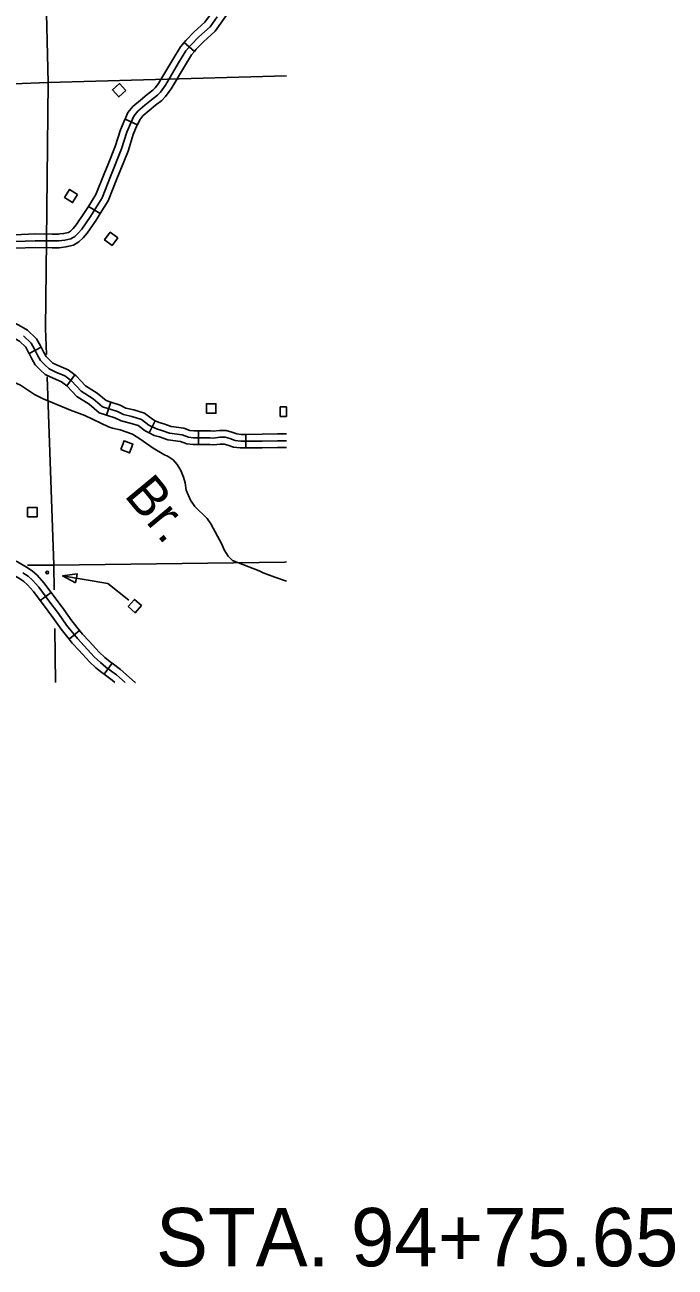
# Model space of a CAD drawing. Extents: x 1370130 to 1380143, y 377636 to 380256.
# Drawn here: x 1377687.4 to 1377888.1, y 378650.3 to 379033.5 of the extents above; entities that cross this region are included whole.
import ezdxf

# ---------------------------------------------------------------- set-up
doc = ezdxf.new("R2010")
doc.units = 0
for name, color, linetype in [('Level 31', 7, 'Continuous'), ('Level 32', 7, 'Continuous'), ('Level 35', 7, 'Continuous'), ('Level 5', 7, 'Continuous'), ('Level 56', 7, 'Continuous'), ('R_Draft', 7, 'Continuous')]:
    doc.layers.add(name, color=color, linetype=linetype)

msp = doc.modelspace()

# ---------------------------------------------------------------- linework, layer by layer
at = {"layer": 'Level 31'}
for p, q in [((1377736.53, 379028.04), (1377739.7, 379025.28)), ((1377722.12, 379002.71), (1377718.3, 379004.46)), ((1377707.05, 378977.5), (1377710.6, 378975.27)), ((1377698.71, 378964.83), (1377698.71, 378964.83))]:
    msp.add_line(p, q, dxfattribs=at)
for points in [[(1377736.53, 379028.04), (1377737.1, 379028.7), (1377739.64, 379031.32), (1377742.97, 379034.36), (1377744.96, 379037.13), (1377746.08, 379038.85)], [(1377684.37, 378966.69), (1377690.58, 378966.92), (1377695.79, 378966.84), (1377697.86, 378966.84), (1377699.7, 378967.07), (1377701.62, 378967.53), (1377702.77, 378968.22), (1377703.84, 378969.22), (1377704.92, 378970.52), (1377707.6, 378974.43), (1377711.2, 378980.19), (1377713.81, 378986.78), (1377717.26, 378995.29), (1377718.87, 379000.43), (1377720.17, 379003.5), (1377721.01, 379005.34), (1377722.24, 379006.88), (1377724.39, 379008.72), (1377726.46, 379010.4), (1377728.3, 379011.79), (1377729.22, 379012.78), (1377730.83, 379014.93), (1377734.81, 379021.76), (1377737.11, 379025.51), (1377738.65, 379027.28), (1377741.1, 379029.81), (1377744.55, 379032.95), (1377746.69, 379035.95)], [(1377739.7, 379025.28), (1377740.19, 379025.86), (1377742.56, 379028.3), (1377746.13, 379031.55), (1377748.43, 379034.76), (1377749.6, 379036.55)], [(1377728.58, 379015.43), (1377729.07, 379016.09), (1377733.01, 379022.83), (1377735.41, 379026.76), (1377736.53, 379028.04)], [(1377739.7, 379025.28), (1377738.81, 379024.27), (1377736.62, 379020.68), (1377732.58, 379013.77), (1377731.94, 379012.91)], [(1377718.3, 379004.46), (1377719.21, 379006.45), (1377720.72, 379008.34), (1377723.04, 379010.33), (1377725.16, 379012.06), (1377726.88, 379013.35), (1377727.6, 379014.13), (1377728.58, 379015.43)], [(1377731.94, 379012.91), (1377730.83, 379011.44), (1377729.71, 379010.22), (1377727.75, 379008.75), (1377725.74, 379007.11), (1377723.76, 379005.41), (1377722.82, 379004.23), (1377722.12, 379002.71)], [(1377713.07, 378990.55), (1377715.28, 378996), (1377716.9, 379001.16), (1377718.25, 379004.35), (1377718.3, 379004.46)], [(1377716.96, 378988.97), (1377719.24, 378994.59), (1377720.84, 378999.71), (1377722.09, 379002.65), (1377722.12, 379002.71)], [(1377707.05, 378977.5), (1377709.32, 378981.14), (1377711.86, 378987.56), (1377713.07, 378990.55)], [(1377710.6, 378975.27), (1377713.08, 378979.23), (1377715.76, 378986), (1377716.96, 378988.97)], [(1377698.19, 378969), (1377699.33, 378969.14), (1377700.82, 378969.5), (1377701.5, 378969.91), (1377702.31, 378970.66), (1377703.24, 378971.78), (1377705.84, 378975.58), (1377707.05, 378977.5)], [(1377710.6, 378975.27), (1377709.36, 378973.28), (1377706.6, 378969.26), (1377705.38, 378967.77), (1377704.04, 378966.53), (1377702.42, 378965.56), (1377700.08, 378965), (1377698.71, 378964.83)], [(1377683.52, 378968.73), (1377684.26, 378968.78), (1377690.56, 378969.02), (1377695.81, 378968.94), (1377697.73, 378968.94), (1377698.19, 378969)], [(1377698.71, 378964.83), (1377698, 378964.74), (1377695.78, 378964.74), (1377690.61, 378964.82), (1377684.49, 378964.59), (1377683.82, 378964.54)]]:
    msp.add_lwpolyline(points, dxfattribs=at)
at = {"layer": 'Level 32'}
for p, q in [((1377692.44, 378934.05), (1377688.73, 378932.09)), ((1377702.78, 378925.56), (1377700.32, 378922.16)), ((1377713.87, 378917.11), (1377712.58, 378913.12)), ((1377727.65, 378911.38), (1377725.79, 378907.62)), ((1377740.97, 378908.24), (1377740.97, 378904.04)), ((1377755.56, 378907.19), (1377755.58, 378902.99)), ((1377692.12, 378855.91), (1377695.48, 378858.44)), ((1377701.02, 378844.03), (1377704.29, 378846.66)), ((1377711.83, 378833.21), (1377714.31, 378836.6))]:
    msp.add_line(p, q, dxfattribs=at)
for points in [[(1377692.44, 378934.05), (1377692.22, 378934.47), (1377690.99, 378936.65), (1377688.22, 378939.29), (1377685.48, 378940.86), (1377684.09, 378941.56), (1377682.16, 378942.39), (1377679.17, 378942.97)], [(1377688.73, 378932.09), (1377688.53, 378932.46), (1377687.64, 378934.05), (1377685.69, 378935.9), (1377683.48, 378937.16), (1377682.31, 378937.76), (1377680.92, 378938.35), (1377678.36, 378938.85)], [(1377768.15, 378905.2), (1377765.38, 378905.2), (1377760.61, 378905.12), (1377754.02, 378905.08), (1377752.28, 378905.33), (1377750.66, 378905.87), (1377749.21, 378906.28), (1377747.55, 378906.28), (1377745.56, 378906.03), (1377744.57, 378906.14), (1377742.98, 378906.14), (1377739.44, 378906.14), (1377737.85, 378906.32), (1377735.9, 378907.03), (1377732.01, 378907.56), (1377729.62, 378908.39), (1377728.04, 378908.85), (1377725.64, 378910.04), (1377723.34, 378911.81), (1377720.44, 378912.68), (1377717.79, 378913.3), (1377715.99, 378914.22), (1377711.39, 378915.71), (1377708.48, 378918.18), (1377704.76, 378920.48), (1377701.82, 378923.67), (1377699.69, 378925.2), (1377696.98, 378926.38), (1377694.86, 378927.44), (1377693.56, 378928.62), (1377692.26, 378929.92), (1377691.44, 378931.46), (1377690.38, 378933.46), (1377689.31, 378935.35), (1377686.96, 378937.59)], [(1377700.32, 378922.16), (1377698.65, 378923.37), (1377696.09, 378924.48), (1377693.66, 378925.69), (1377692.11, 378927.1), (1377690.56, 378928.65), (1377689.58, 378930.47), (1377688.73, 378932.09)], [(1377702.78, 378925.56), (1377700.74, 378927.04), (1377697.87, 378928.28), (1377696.06, 378929.19), (1377695.01, 378930.14), (1377693.97, 378931.19), (1377693.29, 378932.44), (1377692.44, 378934.05)], [(1377713.87, 378917.11), (1377712.43, 378917.58), (1377709.72, 378919.88), (1377706.11, 378922.12), (1377703.22, 378925.25), (1377702.78, 378925.56)], [(1377712.58, 378913.12), (1377710.34, 378913.84), (1377707.24, 378916.48), (1377703.42, 378918.84), (1377700.42, 378922.09), (1377700.32, 378922.16)], [(1377727.65, 378911.38), (1377726.76, 378911.83), (1377724.32, 378913.71), (1377720.98, 378914.71), (1377718.51, 378915.29), (1377716.79, 378916.16), (1377713.87, 378917.11)], [(1377725.79, 378907.62), (1377724.52, 378908.25), (1377722.37, 378909.91), (1377719.9, 378910.65), (1377717.06, 378911.31), (1377715.18, 378912.27), (1377712.58, 378913.12)], [(1377740.97, 378908.24), (1377739.56, 378908.24), (1377738.33, 378908.38), (1377736.41, 378909.08), (1377732.5, 378909.61), (1377730.25, 378910.39), (1377728.8, 378910.81), (1377727.65, 378911.38)], [(1377740.97, 378904.04), (1377739.32, 378904.04), (1377737.37, 378904.26), (1377735.4, 378904.98), (1377731.52, 378905.51), (1377728.98, 378906.39), (1377727.28, 378906.88), (1377725.79, 378907.62)], [(1377755.56, 378907.19), (1377754.16, 378907.18), (1377752.76, 378907.38), (1377751.28, 378907.87), (1377749.5, 378908.38), (1377747.42, 378908.38), (1377745.55, 378908.15), (1377744.69, 378908.24), (1377742.98, 378908.24), (1377740.97, 378908.24)], [(1377755.58, 378902.99), (1377753.88, 378902.98), (1377751.79, 378903.27), (1377750.04, 378903.86), (1377748.92, 378904.18), (1377747.68, 378904.18), (1377745.57, 378903.92), (1377744.45, 378904.04), (1377742.98, 378904.04), (1377740.97, 378904.04)], [(1377768.15, 378907.3), (1377765.36, 378907.3), (1377760.59, 378907.22), (1377755.56, 378907.19)], [(1377768.15, 378903.1), (1377765.4, 378903.1), (1377760.64, 378903.02), (1377755.58, 378902.99)], [(1377683.12, 378868.6), (1377683.35, 378868.56), (1377685.15, 378867.9), (1377687.91, 378866.25), (1377689.64, 378865.1), (1377691.2, 378863.71), (1377693.28, 378861.36), (1377695.48, 378858.44)], [(1377682.22, 378864.5), (1377683.33, 378864.09), (1377685.68, 378862.69), (1377687.07, 378861.77), (1377688.21, 378860.75), (1377690.03, 378858.7), (1377692.12, 378855.91)], [(1377686.79, 378864.47), (1377688.36, 378863.44), (1377689.7, 378862.23), (1377691.66, 378860.03), (1377694.78, 378855.87), (1377697.73, 378851.89), (1377700.25, 378848.34), (1377703.59, 378844.19), (1377705.68, 378841.95), (1377708.8, 378838.54), (1377710.69, 378836.8), (1377712.42, 378835.38), (1377715.62, 378833.03), (1377718.35, 378830.61)], [(1377695.48, 378858.44), (1377696.46, 378857.13), (1377699.43, 378853.13), (1377701.92, 378849.61), (1377704.29, 378846.66)], [(1377692.12, 378855.91), (1377693.1, 378854.62), (1377696.03, 378850.66), (1377698.57, 378847.07), (1377701.02, 378844.03)], [(1377704.29, 378846.66), (1377705.17, 378845.56), (1377707.22, 378843.37), (1377710.29, 378840.02), (1377712.06, 378838.38), (1377713.71, 378837.04), (1377714.31, 378836.6)], [(1377701.02, 378844.03), (1377702, 378842.81), (1377704.14, 378840.52), (1377707.31, 378837.06), (1377709.31, 378835.21), (1377711.14, 378833.72), (1377711.83, 378833.21)], [(1377714.31, 378836.6), (1377716.94, 378834.67), (1377721.48, 378830.63), (1377721.51, 378830.61)], [(1377711.83, 378833.21), (1377714.3, 378831.4), (1377715.18, 378830.61)]]:
    msp.add_lwpolyline(points, dxfattribs=at)
at = {"layer": 'Level 35'}
for points in [[(1377714.47, 378909.08), (1377713.16, 378909.48), (1377705.93, 378913.01), (1377701.46, 378914.69), (1377693.05, 378918.15), (1377690.37, 378919.51), (1377686.04, 378922.36), (1377683.82, 378923.34), (1377679.02, 378924.02), (1377675.01, 378923.9), (1377672.23, 378923.7), (1377669.12, 378923.32), (1377664.48, 378922.67), (1377660.92, 378922.12), (1377657.56, 378921.54), (1377652.13, 378920.36), (1377648.25, 378917.89), (1377646.35, 378916.68), (1377644.23, 378915.76)], [(1377768.15, 378861.89), (1377764.51, 378863.1), (1377760.89, 378864.45), (1377759.72, 378865.1), (1377751.48, 378868.27), (1377750.11, 378869.61), (1377748.92, 378871.53), (1377748.18, 378873.36), (1377744.79, 378879.55), (1377743.64, 378881.18), (1377739.88, 378884.89), (1377738.49, 378886.91), (1377737.14, 378890), (1377736.84, 378892.18), (1377736.38, 378893.94), (1377735.53, 378895.99), (1377734.42, 378897.91), (1377733.13, 378899.28), (1377731.59, 378900.37), (1377730.23, 378901.02), (1377726.96, 378902.94), (1377722.91, 378905.8), (1377720.63, 378907.22), (1377716.75, 378908.62), (1377714.47, 378909.08)]]:
    msp.add_lwpolyline(points, dxfattribs=at)
at = {"layer": 'Level 5'}
for points in [[(1377693.93, 379041.44), (1377694.59, 379015.69)], [(1377633.11, 379013.36), (1377694.59, 379015.69)], [(1377694.59, 379015.69), (1377694.07, 378966.85), (1377693.76, 378939.81), (1377694.05, 378931.81)], [(1377694.59, 379015.69), (1377768.15, 379017.75)], [(1377694.29, 378924.89), (1377696.36, 378866.88)], [(1377696.36, 378866.88), (1377688.18, 378866.82)], [(1377768.15, 378867.82), (1377767.64, 378867.8), (1377696.36, 378866.88)], [(1377696.36, 378866.88), (1377696.45, 378859.25)], [(1377696.59, 378847.33), (1377696.8, 378830.61)]]:
    msp.add_lwpolyline(points, dxfattribs=at)
at = {"layer": 'Level 56'}
for p, q in [((1377766.15, 378915.66), (1377768.15, 378915.66)), ((1377766.15, 378912.74), (1377766.15, 378915.66)), ((1377768.15, 378915.66), (1377768.15, 378912.74)), ((1377768.15, 378912.74), (1377766.15, 378912.74))]:
    msp.add_line(p, q, dxfattribs=at)
for points in [[(1377718.53, 379013.26), (1377716.38, 379011.29), (1377714.41, 379013.45), (1377716.56, 379015.42)], [(1377703.65, 378981.18), (1377702.1, 378978.71), (1377699.63, 378980.26), (1377701.17, 378982.73)], [(1377716.07, 378967.79), (1377714.33, 378965.45), (1377711.99, 378967.19), (1377713.73, 378969.53)], [(1377743.41, 378913.7), (1377743.41, 378916.61), (1377746.33, 378916.61), (1377746.33, 378913.7)], [(1377716.97, 378902.5), (1377718.01, 378905.22), (1377720.74, 378904.18), (1377719.7, 378901.45)], [(1377688.25, 378881.72), (1377688.25, 378884.63), (1377691.17, 378884.63), (1377691.17, 378881.72)], [(1377703.03, 378861.38), (1377703.5, 378864.19), (1377699.04, 378863.5)], [(1377719.25, 378854.09), (1377721.18, 378856.28), (1377723.37, 378854.34), (1377721.44, 378852.16)]]:
    msp.add_lwpolyline(points, close=True, dxfattribs=at)
msp.add_lwpolyline([(1377699.04, 378863.5), (1377712.98, 378861.14), (1377719.46, 378856.04)], dxfattribs=at)
msp.add_circle((1377694.31, 378864.57), 0.42, dxfattribs=at)

# ---------------------------------------------------------------- texts
at = {"layer": 'Level 35'}
msp.add_text('Br.', height=11.827, rotation=309.6801, dxfattribs=at).set_placement((1377717.79, 378888.3))
at = {"layer": 'R_Draft'}
msp.add_text('STA. 94+75.65', height=18, rotation=0.0006, dxfattribs=at).set_placement((1377727.85, 378650.53))

doc.saveas('drawing.dxf')
